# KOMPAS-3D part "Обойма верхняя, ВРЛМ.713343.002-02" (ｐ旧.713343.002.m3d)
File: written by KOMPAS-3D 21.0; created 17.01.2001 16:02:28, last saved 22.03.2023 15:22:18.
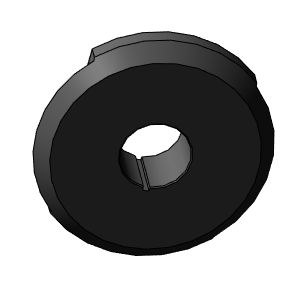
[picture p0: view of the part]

Document properties: Полное имя файла: D:\2023\Чертежи dwg cdw\ВРЛМ.713343.002.m3d

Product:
- Part/product: Обойма верхняя  | designation ВРЛМ.713343.002-02
    Материал: Сталь 40Х13 ГОСТ 5632-2014 (density 7650 kg/m3)
    Масса: 0.133437
    additional columns: 22; 23; 2
- Part/product: Обойма верхняя  | designation ВРЛМ.713343.002-01
    Материал: Сталь 40Х13 ГОСТ 5632-2014 (density 7650 kg/m3)
    Масса: 0.141077
    additional columns: 20; 20.9; 1.6
- Part/product: Обойма верхняя  | designation ВРЛМ.713343.002
    Материал: Сталь 40Х13 ГОСТ 5632-2014 (density 7650 kg/m3)
    Масса: 0.151638
    additional columns: 17; 17.9; 1.6

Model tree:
1. Фронтальная плоскость
2. Горизонтальная плоскость
3. Профильная плоскость
4. Начало координат
5. Эскиз:1
6. Операция вращения:1
     Угол 1 = 360
7. Эскиз:2
8. Вырезать элемент выдавливания:1
     Расстояние 2 = 4.5
9. Эскиз:3
10. Вырезать элемент выдавливания:2  (labels: Сталь 40Х13 ГОСТ 5632-2014; E9; D12)
     Расстояние 2 = 15

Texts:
  ВРЛМ.713343.002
